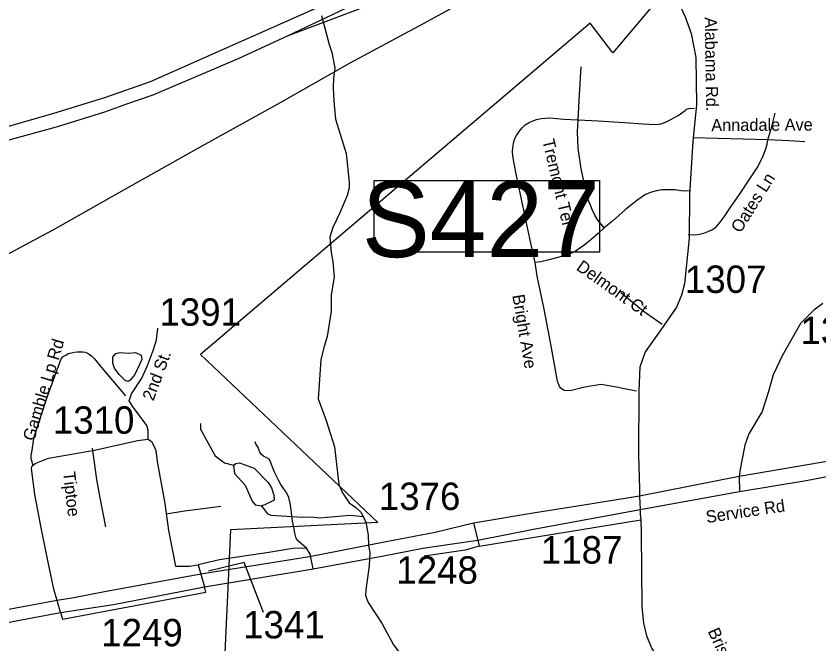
# Model space of a CAD drawing. Extents: x 1268485 to 1426702, y 514839 to 616766.
# Drawn here: x 1323145 to 1327469, y 555405 to 558786 of the extents above; entities that cross this region are included whole.
import ezdxf

# ---------------------------------------------------------------- set-up
doc = ezdxf.new("R2010")
doc.units = 0
for name, color, linetype in [('Old_Level_10', 7, 'Continuous'), ('Old_Level_11', 7, 'Continuous'), ('Old_Level_27', 7, 'Continuous'), ('Old_Level_28', 7, 'Continuous'), ('Old_Level_31', 7, 'Continuous'), ('Old_Level_32', 7, 'Continuous'), ('Old_Level_35', 7, 'Continuous'), ('Old_Level_39', 7, 'Continuous'), ('Old_Level_47', 7, 'Continuous'), ('Old_Level_48', 7, 'Continuous'), ('Old_Level_49', 7, 'Continuous'), ('Old_Level_56', 7, 'Continuous'), ('Old_Level_62', 7, 'Continuous'), ('Old_Level_8', 7, 'Continuous')]:
    doc.layers.add(name, color=color, linetype=linetype)

msp = doc.modelspace()

# ---------------------------------------------------------------- linework, layer by layer
at = {"layer": 'Old_Level_11'}
msp.add_lwpolyline([(1324477.193, 555574.573), (1324373.276, 555843.73), (1324181.533, 555797.856)], dxfattribs=at)
at = {"layer": 'Old_Level_27'}
for points in [[(1324606.413, 558678.81), (1325477.949, 559094.605), (1326027.137, 559359.853), (1326283.219, 559473.524)], [(1324928.762, 558903.435), (1323867.637, 558431.695), (1323621.398, 558345.731), (1323345.796, 558260.766), (1323009.407, 558163.805)], [(1323033.103, 558099.832), (1323362.796, 558189.795), (1323623.459, 558269.762), (1323740.912, 558312.745), (1323883.607, 558362.724), (1324346.146, 558559.33), (1324606.413, 558678.81)]]:
    msp.add_lwpolyline(points, dxfattribs=at)
at = {"layer": 'Old_Level_28'}
for p, q in [((1327039.318, 556307.287), (1326502.813, 556200.074)), ((1326506.337, 556128.275), (1327041.282, 556225.753)), ((1325557.404, 555953.314), (1325632.521, 555964.161)), ((1324725.383, 555874.648), (1324139.525, 555780.468)), ((1324159.272, 555712.009), (1324745.046, 555809.449))]:
    msp.add_line(p, q, dxfattribs=at)
for points in [[(1328515.839, 556481.776), (1328340.963, 556489.243), (1328106.51, 556485.391), (1327987.933, 556471.765), (1327761.567, 556429.148), (1327555.166, 556395.052), (1327039.318, 556307.287)], [(1327041.282, 556225.753), (1327400.927, 556284.464), (1327709.382, 556344.09), (1327977.418, 556391.092), (1328188.787, 556408.633), (1328494.196, 556397.593)], [(1326502.813, 556200.074), (1326202.76, 556152.103), (1325941.345, 556110.557), (1325608.598, 556055.213)], [(1325632.521, 555964.161), (1325932.146, 556023.687), (1326506.337, 556128.275)], [(1325608.598, 556055.213), (1325402.175, 556005.189), (1325137.916, 555954.758), (1324725.383, 555874.648)], [(1324745.046, 555809.449), (1325115.453, 555876.976), (1325336.55, 555921.423), (1325557.404, 555953.314)], [(1324139.525, 555780.468), (1323620.496, 555686.328), (1323455.401, 555653.472), (1323365.993, 555638.278)], [(1323384.558, 555573.538), (1323669.518, 555617.132), (1324159.272, 555712.009)], [(1323365.993, 555638.278), (1323095.632, 555588.07), (1322845.109, 555545.065), (1322663.446, 555515.085), (1322245.653, 555444.225), (1322106.871, 555415.303), (1321852.436, 555373.366), (1321589.355, 555317.967), (1321462.511, 555294.034), (1321235.248, 555256.424), (1321009.747, 555223.944)], [(1322863.965, 555473.096), (1323056.875, 555513.269), (1323384.558, 555573.538)]]:
    msp.add_lwpolyline(points, dxfattribs=at)
at = {"layer": 'Old_Level_31'}
msp.add_lwpolyline([(1325073.563, 557900.044), (1326287.288, 557900.044), (1326287.288, 557513.878), (1325073.563, 557513.878), (1325073.563, 557900.044)], dxfattribs=at)
at = {"layer": 'Old_Level_32'}
for p, q in [((1327039.318, 556307.287), (1327041.282, 556225.753)), ((1326502.813, 556200.074), (1326506.337, 556128.275)), ((1324125.176, 555830.209), (1324139.525, 555780.468)), ((1324139.525, 555780.468), (1324159.272, 555712.009)), ((1323384.558, 555573.538), (1323365.993, 555638.278))]:
    msp.add_line(p, q, dxfattribs=at)
for points in [[(1326592.344, 559062.325), (1326676.996, 558937.521), (1326749.483, 558781.713), (1326781.509, 558692.827), (1326806.293, 558562.264), (1326810.377, 558308.058), (1326789.826, 558112.376), (1326771.181, 557822.609), (1326769.708, 557590.526), (1326745.347, 557343.374), (1326729.574, 557283.747), (1326701.533, 557217.982), (1326654.213, 557147.832), (1326613.903, 557091.713), (1326532.764, 556977.902), (1326505.243, 556895.294), (1326499.984, 556767.271), (1326496.48, 556423.538), (1326501.933, 556237.682), (1326502.813, 556200.074)], [(1327489.967, 557237.673), (1327441.037, 557202.639), (1327369.347, 557130.445), (1327271.125, 556956.675), (1327222.052, 556854.958), (1327197.516, 556763.764), (1327164.216, 556656.786), (1327092.073, 556537.106), (1327069.936, 556475.743), (1327044.545, 556345.381), (1327039.318, 556307.287)], [(1323856.698, 556506.932), (1323856.259, 556556.509), (1323849.211, 556581.296), (1323772.136, 556684.721), (1323753.637, 556713.783), (1323766.85, 556752.247), (1323822.345, 556836.868), (1323852.735, 556905.248), (1323884.447, 556989.869), (1323900.742, 557042.01), (1323908.67, 557105.262)], [(1323365.993, 555638.278), (1323350.527, 555692.216), (1323320.101, 555835.984), (1323282.912, 556011.888), (1323245.519, 556209.698), (1323228.739, 556350.104), (1323231.723, 556363.331), (1323247.579, 556377.007), (1323319.81, 556406.069), (1323567.288, 556448.346), (1323799.442, 556500.949), (1323856.698, 556506.932)], [(1323856.698, 556506.932), (1323873.435, 556494.965), (1323887.528, 556472.742), (1323897.218, 556447.099), (1323905.145, 556387.266), (1323945.665, 556160.755), (1323965.925, 556016.301), (1324003.689, 555823.162), (1324077.638, 555823.162), (1324125.176, 555830.209)], [(1326506.337, 556128.275), (1326506.996, 556104.359), (1326509.808, 556072.52)], [(1326509.808, 556072.52), (1326512.253, 555999.135), (1326515.404, 555605.268), (1326523.432, 555517.064), (1326540.294, 555449.338), (1326568.336, 555380.943), (1326652.46, 555249.412), (1326715.553, 555145.942), (1326783.905, 555023.18), (1326825.966, 554939.877), (1326887.307, 554800.456), (1326957.411, 554606.667), (1327025.42, 554403.824)]]:
    msp.add_lwpolyline(points, dxfattribs=at)
at = {"layer": 'Old_Level_35'}
for p, q in [((1326790.531, 558131.42), (1327194.791, 558120.553)), ((1324728.117, 555888.611), (1324728.117, 555888.611))]:
    msp.add_line(p, q, dxfattribs=at)
for points in [[(1326173.017, 558226.82), (1326180.091, 558364.513), (1326189.113, 558513.125)], [(1326173.017, 558226.82), (1326279.336, 558222.053), (1326421.335, 558213.339), (1326520.58, 558206.213), (1326588.862, 558202.266), (1326617.467, 558206.213), (1326641.971, 558214.927), (1326671.396, 558229.178), (1326711.176, 558249.838), (1326748.085, 558278.288), (1326756.595, 558284.697), (1326767.975, 558288.951), (1326799.041, 558291.002)], [(1327194.791, 558120.553), (1327211.708, 558177.198), (1327233.136, 558263.576)], [(1325940.488, 557458.542), (1325936.489, 557476.022), (1325924.596, 557528.362), (1325893.633, 557672.052), (1325840.525, 557928.367), (1325826.991, 557992.703), (1325819.917, 558033.2), (1325818.994, 558055.397), (1325820.635, 558077.645), (1325823.71, 558100.611), (1325830.17, 558122.859), (1325839.602, 558143.518), (1325854.776, 558164.946), (1325869.847, 558184.734), (1325887.277, 558199.805), (1325904.706, 558210.929), (1325923.776, 558219.695), (1325948.382, 558229.178), (1325972.988, 558234.767), (1326019.843, 558237.945), (1326095.199, 558231.588), (1326173.017, 558226.82)], [(1326311.837, 557645.088), (1326295.843, 557664.978), (1326279.029, 557687.021), (1326262.009, 557713.934), (1326247.04, 557743.872), (1326238.018, 557767.811), (1326228.176, 557793.75), (1326222.127, 557817.691), (1326205.107, 557889.51), (1326188.088, 557964.354), (1326172.299, 558074.108), (1326168.3, 558161.921), (1326173.017, 558226.82)], [(1326765.207, 557609.101), (1326791.044, 557607.871), (1326816.983, 557610.691), (1326848.663, 557617.201), (1326876.55, 557627.351), (1326896.03, 557636.68), (1326918.278, 557653.392), (1326937.758, 557675.692), (1326958.161, 557704.502), (1326994.353, 557758.379), (1327044.488, 557830.814), (1327092.88, 557904.12), (1327135.634, 557968.25), (1327155.114, 558003.519), (1327168.955, 558033.251), (1327182.898, 558070.366), (1327190.383, 558096.356), (1327194.791, 558120.553)], [(1327194.791, 558120.553), (1327306.545, 558115.887), (1327392.871, 558111.274)], [(1326776.895, 557844.193), (1326753.109, 557842.707), (1326726.965, 557845.885), (1326693.644, 557849.832), (1326659.503, 557850.601), (1326623.003, 557849.832), (1326594.501, 557845.885), (1326567.537, 557838.708), (1326534.831, 557824.457), (1326488.079, 557793.494), (1326424.616, 557741.872), (1326357.153, 557682.356), (1326311.837, 557645.088)], [(1326311.837, 557645.088), (1326279.336, 557614.894), (1326229.406, 557572.807), (1326196.7, 557546.612), (1326174.657, 557530.771), (1326155.485, 557518.058), (1326136.517, 557508.575), (1326110.271, 557498.988), (1326090.483, 557492.683), (1326063.519, 557485.557), (1326013.486, 557472.793), (1325970.63, 557462.489), (1325940.488, 557458.542)], [(1326485.721, 556766.439), (1326430.972, 556777.564), (1326379.402, 556788.688), (1326337.263, 556795.814), (1326296.048, 556801.401), (1326272.262, 556798.992), (1326228.483, 556791.046), (1326191.984, 556783.921), (1326136.517, 556770.438), (1326108.733, 556767.26), (1326097.66, 556769.618), (1326087.202, 556775.206), (1326078.488, 556782.331), (1326072.234, 556791.866), (1326068.235, 556801.401), (1326064.954, 556810.116), (1326061.878, 556820.42), (1326024.661, 557018.859), (1325988.88, 557207.763), (1325952.381, 557386.312), (1325940.488, 557458.542)], [(1326624.644, 557124.46), (1326522.22, 557197.459), (1326402.367, 557295.064)], [(1323235.133, 556368.895), (1323231.032, 556384.992), (1323226.521, 556401.703), (1323226.521, 556418.415), (1323229.904, 556437.383), (1323242.105, 556520.941), (1323312.232, 556734.811), (1323386.871, 556940.888), (1323399.175, 556952.063), (1323412.503, 556960.983), (1323425.831, 556968.826), (1323442.646, 556973.234), (1323458.23, 556976.618), (1323473.916, 556977.695), (1323489.397, 556978.823), (1323504.981, 556977.695), (1323519.54, 556975.49), (1323535.124, 556967.698), (1323548.452, 556958.727), (1323567.42, 556940.939), (1323605.252, 556894.136), (1323734.844, 556740.274)], [(1324709.765, 555921.446), (1324657.784, 555964.993), (1324651.223, 555979.86), (1324646.609, 556002.108), (1324641.995, 556024.458), (1324634.511, 556067.109), (1324628.052, 556110.837), (1324624.361, 556140.518), (1324620.67, 556162.818), (1324613.083, 556193.421), (1324601.087, 556220.386), (1324585.298, 556242.686), (1324571.355, 556264.062), (1324559.257, 556282.619), (1324547.261, 556307.687), (1324537.009, 556329.986), (1324525.833, 556356.95), (1324520.297, 556371.766), (1324512.915, 556390.323), (1324507.276, 556399.601), (1324496.101, 556408.008), (1324479.389, 556414.519), (1324467.393, 556425.643), (1324458.166, 556438.613), (1324451.604, 556451.634), (1324447.913, 556463.68), (1324437.661, 556478.546), (1324432.124, 556493.413)], [(1323554.502, 556460.041), (1323563.011, 556393.962), (1323577.467, 556290.309), (1323596.332, 556191.115), (1323626.475, 556035.173)], [(1323952.713, 556106.274), (1324051.343, 556121.192), (1324135.619, 556132.008), (1324247.373, 556146.311)]]:
    msp.add_lwpolyline(points, dxfattribs=at)
at = {"layer": 'Old_Level_39'}
for p, q in [((1325608.598, 556055.213), (1325632.521, 555964.161)), ((1324745.046, 555809.449), (1324728.117, 555888.611))]:
    msp.add_line(p, q, dxfattribs=at)
for points in [[(1325632.521, 555964.161), (1325639.731, 555931.105), (1326509.808, 556072.52)], [(1325639.731, 555931.105), (1325563.482, 555910.162), (1325342.212, 555877.251)], [(1324728.117, 555888.611), (1324709.765, 555921.446), (1324634.591, 555918.554), (1324505.928, 555896.862), (1324239.928, 555857.817), (1324125.176, 555830.209)], [(1323777.711, 555610.504), (1324166.838, 555683.363), (1324159.272, 555712.009)], [(1323384.558, 555573.538), (1323395.485, 555538.938), (1323777.711, 555610.504)]]:
    msp.add_lwpolyline(points, dxfattribs=at)
at = {"layer": 'Old_Level_47'}
msp.add_lwpolyline([(1324606.413, 558678.81), (1325150.825, 558886.708), (1325518.541, 559034.864), (1325736.798, 559084.16), (1325868.626, 559094.885), (1325991.88, 559102.392), (1326122.101, 559112.044), (1326255.001, 559124.914), (1326313.948, 559134.566), (1326354.676, 559146.363), (1326407.193, 559169.957), (1326452.207, 559198.914), (1326475.901, 559218.127)], dxfattribs=at)
at = {"layer": 'Old_Level_48'}
for points in [[(1330982.204, 561311.916), (1330958.548, 561392.204), (1330559.787, 561212.359), (1330590.2, 561160.975), (1330299.577, 561032.514), (1330286.06, 561087.11), (1329542.605, 560724.209), (1329574.451, 560663.675), (1329252.922, 560518.236), (1329212.141, 560634.871), (1326800.675, 559475.871), (1326611.792, 559257.337), (1326553.956, 559196.331), (1326597.361, 559147.604), (1326593.415, 558866.488), (1326359.163, 558587.933), (1326236.675, 558748.008)], [(1326236.675, 558748.008), (1324137.472, 556962.865), (1325093.959, 556059.326), (1324299.847, 556019.456), (1324127.49, 552278.436), (1323814.402, 551729.702), (1323777.875, 551985.559), (1323668.578, 552169.345), (1323428.367, 552249.541), (1323423.573, 552091.276), (1323387.628, 552343.061), (1323266.508, 552351.069), (1323181.28, 552277.967), (1323023.087, 553119.55)]]:
    msp.add_lwpolyline(points, dxfattribs=at)
at = {"layer": 'Old_Level_49'}
for points in [[(1330982.204, 561311.916), (1330958.548, 561392.204), (1330559.787, 561212.359), (1330590.2, 561160.975), (1330299.577, 561032.514), (1330286.06, 561087.11), (1329542.605, 560724.209), (1329574.451, 560663.675), (1329252.922, 560518.236), (1329212.141, 560634.871), (1326800.675, 559475.871), (1326611.792, 559257.337), (1326553.956, 559196.331), (1326597.361, 559147.604), (1326593.415, 558866.488), (1326359.163, 558587.933), (1326236.675, 558748.008)], [(1326236.675, 558748.008), (1324137.472, 556962.865), (1325093.959, 556059.326), (1324299.847, 556019.456), (1324127.49, 552278.436), (1323814.402, 551729.702), (1323777.875, 551985.559), (1323668.578, 552169.345), (1323428.367, 552249.541), (1323423.573, 552091.276), (1323387.628, 552343.061), (1323266.508, 552351.069), (1323181.28, 552277.967), (1323023.087, 553119.55)]]:
    msp.add_lwpolyline(points, dxfattribs=at)
at = {"layer": 'Old_Level_56'}
msp.add_lwpolyline([(1322933.443, 557415.562), (1323344.853, 557634.199), (1323742.183, 557859.121), (1324147.795, 558087.879), (1324553.322, 558312.436), (1324944.571, 558533.478), (1325362.103, 558757.994), (1325797.996, 558999.95), (1326073.187, 559131.681), (1326235.889, 559241.864), (1326558.622, 559518.511), (1326938.245, 559837.835), (1327309.186, 560133.522), (1327674.242, 560425.125), (1328033.46, 560724.849), (1328413.001, 561040.172), (1328552.741, 561155.884)], dxfattribs=at)
at = {"layer": 'Old_Level_62'}
for points in [[(1324790.248, 558789.432), (1324830.541, 558632.363), (1324845.612, 558590.07), (1324861.709, 558507.588), (1324854.327, 558451.712), (1324853.096, 558399.731), (1324855.454, 558327.603), (1324865.194, 558231.383), (1324922.917, 558045.914), (1324939.321, 557891.458), (1324938.706, 557861.469), (1324927.735, 557819.741), (1324889.493, 557726.545), (1324851.558, 557647.343), (1324834.437, 557595.722), (1324842.434, 557513.496), (1324851.353, 557463.309), (1324857.505, 557381.083), (1324841.203, 557283.427), (1324841.101, 557197.356), (1324819.98, 557059.766), (1324800.5, 556994.15), (1324786.967, 556934.48), (1324772.101, 556724.711), (1324815.367, 556607.627), (1324860.068, 556466.5), (1324883.444, 556263.908), (1324902.514, 556219.412), (1324939.116, 556164.509), (1324974.59, 556139.647), (1325001.964, 556115.041), (1325013.447, 556090.793)], [(1323784.57, 556855.74), (1323757.811, 556824.367), (1323747.661, 556818.523), (1323731.872, 556822.983), (1323700.601, 556855.689), (1323675.38, 556890.291), (1323665.947, 556916.538), (1323666.665, 556948.526), (1323681.224, 556968.211), (1323703.369, 556973.696), (1323755.35, 556970.466), (1323787.338, 556973.747), (1323819.121, 556960.983), (1323822.607, 556936.94), (1323784.57, 556855.74)], [(1324138.695, 556591.377), (1324137.977, 556561.387), (1324216.615, 556417.441), (1324267.878, 556380.224), (1324315.552, 556367.101)], [(1324315.552, 556367.101), (1324327.855, 556376.79), (1324347.848, 556380.378), (1324427.203, 556352.491), (1324503.483, 556274.674), (1324520.809, 556246.325), (1324533.83, 556205.93), (1324535.368, 556179.94), (1324484.72, 556155.077), (1324466.573, 556149.489)], [(1324315.552, 556367.101), (1324320.474, 556323.014), (1324379.118, 556259.551), (1324417.053, 556174.608), (1324432.637, 556154.308), (1324466.573, 556149.489)], [(1324466.573, 556149.489), (1324497.639, 556106.736), (1324517.324, 556098.329), (1324689.26, 556088.281), (1324733.346, 556089.255), (1324779.175, 556084.18), (1324943.627, 556098.38), (1325013.447, 556090.793)], [(1325013.447, 556090.793), (1325028.826, 556060.394), (1325041.232, 555990.01), (1325043.897, 555935.979), (1325050.972, 555897.788), (1325047.383, 555827.814), (1325028.211, 555694.222), (1325027.596, 555666.13), (1325040.719, 555627.888), (1325116.076, 555514.033), (1325177.489, 555400.588), (1325305.749, 555233.47), (1325428.575, 555096.547)]]:
    msp.add_lwpolyline(points, dxfattribs=at)

# ---------------------------------------------------------------- texts
at = {"layer": 'Old_Level_10'}
for s, height, rotation, p in [('Annadale Ave', 65.61666, 0.371978, (1326889.671, 558166.111)), ('Tremont Ter', 65.61666, 283.360367, (1325978.653, 558115.949)), ('Oates Ln', 65.6167, 57.778517, (1327046.233, 557613.635)), ('Delmont Ct', 65.6167, 324.734267, (1326157.776, 557423.027)), ('Bright Ave', 65.6167, 279.70165, (1325817.21, 557281.919)), ('Gamble Lp Rd', 65.61665, 73.234728, (1323241.928, 556493.892)), ('Tiptoe', 65.6167, 276.508483, (1323397.677, 556329.714)), ('Service Rd', 65.6167, 8.502561, (1326865.488, 556055.843)), ('Bristol Cir', 65.61666, 294.139044, (1326869.288, 555474.243))]:
    msp.add_text(s, height=height, rotation=rotation, dxfattribs=at).set_placement(p)
at = {"layer": 'Old_Level_11'}
for s, height, rotation, p in [('Alabama Rd.', 65.61666, 270.920375, (1326853.853, 558779.612)), ('2nd St.', 65.6167, 69.456494, (1323884.075, 556709.942))]:
    msp.add_text(s, height=height, rotation=rotation, dxfattribs=at).set_placement(p)
at = {"layer": 'Old_Level_31'}
msp.add_text('S427', height=410.1042, dxfattribs=at).set_placement((1325007.209, 557487.93))
at = {"layer": 'Old_Level_8'}
for s, p in [('1307', (1326747.263, 557295.211)), ('1391', (1323917.071, 557118.481)), ('1311', (1327369.492, 557019.779)), ('1310', (1323342.842, 556536.822)), ('1376', (1325098.724, 556126.496)), ('1187', (1325971.423, 555837.932)), ('1248', (1325193.151, 555729.418)), ('1341', (1324367.661, 555435.04)), ('1249', (1323603.421, 555392.289))]:
    msp.add_text(s, height=147.6375, dxfattribs=at).set_placement(p)

doc.saveas('drawing.dxf')
